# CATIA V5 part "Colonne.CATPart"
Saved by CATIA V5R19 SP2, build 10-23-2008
Part number: Colonne
Bounding box of the stored display mesh (mm): x -70 to 70, y -69.804 to 69.804, z 10 to 1085
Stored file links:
  G:\EU_thinkMotion\CFAO_2010\MMS_groupe2\MMS_groupe2\OK\nrosalie\nrosalie_cfao_support_d_arme_legere_final\Colonne.CATPart
  G:\EU_thinkMotion\CFAO_2010\MMS_groupe2\MMS_groupe2\OK\nrosalie\nrosalie_cfao_support_d_arme_legere_final\nrosalie_Support_d_arme_legere.CATProduct
  G:\EU_thinkMotion\CFAO_2010\MMS_groupe2\MMS_groupe2\OK\nrosalie\nrosalie_cfao_support_d_arme_legere_final\Squelette_Colone.CATPart
  G:\EU_thinkMotion\CFAO_2010\MMS_groupe2\MMS_groupe2\OK\nrosalie\nrosalie_cfao_support_d_arme_legere_final\Chapeau_liaison_pivot_systeme.CATPart
  G:\EU_thinkMotion\CFAO_2010\MMS_groupe2\MMS_groupe2\OK\nrosalie\nrosalie_cfao_support_d_arme_legere_final\Plaque_liaison_au_sol.CATPart
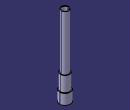
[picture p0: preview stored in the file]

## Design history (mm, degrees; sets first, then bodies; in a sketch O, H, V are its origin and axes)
Set1
  Sketch1 on xy-plane, origin (0, 0, 0), H (1, 0, 0), V (0, 1, 0)
    circle A1 centre (0, 0) radius 70
    reference projected point E1 (0, 0) from Point1
    radius A1 = 70
    concentricity: A1 E1
Set2
  Point1 "Centre_plan_limite_superieur_colonne": linked copy from another document
  Plane1 "Plan_limite_inferieur_liaison_pivot_colone_systeme": linked copy from another document
  Plane2 "Plan_inferieur_liaison_pivot_siege": linked copy from another document
  Plane3 "Plan_superieur_liaison_pivot_siege": linked copy from another document
  DatumSurface1: linked copy from another document
Body1 (main body)
  Pad1: profile Sketch1, direction (0, 0, 1), up to Plane1, offset -15, opposite side up to face of DatumSurface1
  Sketch2 on end face of Pad1, origin (0, 0, 1085), H (1, 0, 0), V (0, 1, 0)
    circle A1 centre (0, 0) radius 60
    reference projected point E1 (0, 0) from Point1
    reference projected circle E2 centre (0, 0) radius 70 from edge [face of Pad1 from Sketch1.A1 | end face of Pad1]
    distance A1 E2 = 10
    concentricity: A1 E1
  Pocket1: profile Sketch2, direction (0, 0, -1), up to Plane2, outer side
  Sketch3 on Plane1, origin (0, 0, 1100), H (1, 0, 0), V (0, 1, 0)
    circle A1 centre (0, 0) radius 50
    reference projected point E1 (0, 0) from Point1
    reference projected circle E2 centre (0, 0) radius 60 from edge [face of Pocket1 from Sketch2.A1 | end face of Pad1]
    distance A1 E2 = 10
    concentricity: A1 E1
  Pocket2: profile Sketch3, direction (0, 0, -1), up to Plane3, outer side
  Sketch4 on Plane1, origin (0, 0, 1100), H (1, 0, 0), V (0, 1, 0)
    circle A1 centre (0, 0) radius 40
    point P1 (0, 0)
    reference projected circle E1 centre (0, 0) radius 50 from edge [face of Pocket2 from Sketch3.A1 | end face of Pad1]
    distance A1 E1 = 10
    coincidence: P1 H
    concentricity: A1 O
  Pocket3: profile Sketch4, direction (0, 0, -1), up to start face of Pad1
